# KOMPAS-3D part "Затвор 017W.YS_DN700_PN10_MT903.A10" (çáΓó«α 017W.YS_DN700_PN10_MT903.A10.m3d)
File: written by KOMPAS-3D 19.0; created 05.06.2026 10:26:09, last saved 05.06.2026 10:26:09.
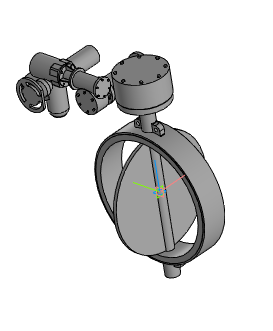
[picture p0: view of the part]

Document properties: Автор: Энергия; Полное имя файла: ..\..\..\3d для проектировщиков\x.x Тип 017W.Y(S) Затвор дисковый поворотный межфланцевый\Затвор 017W.Y(S)_DN32-DN1200_QT.A_MT903.A\Затвор 017W.YS_DN700_PN10_MT903.A10.a3d

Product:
- Part/product: Затвор 017W.YS_DN700_PN10_MT903.A10
    Масса: 461.145

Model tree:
1. Операция без истории:1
